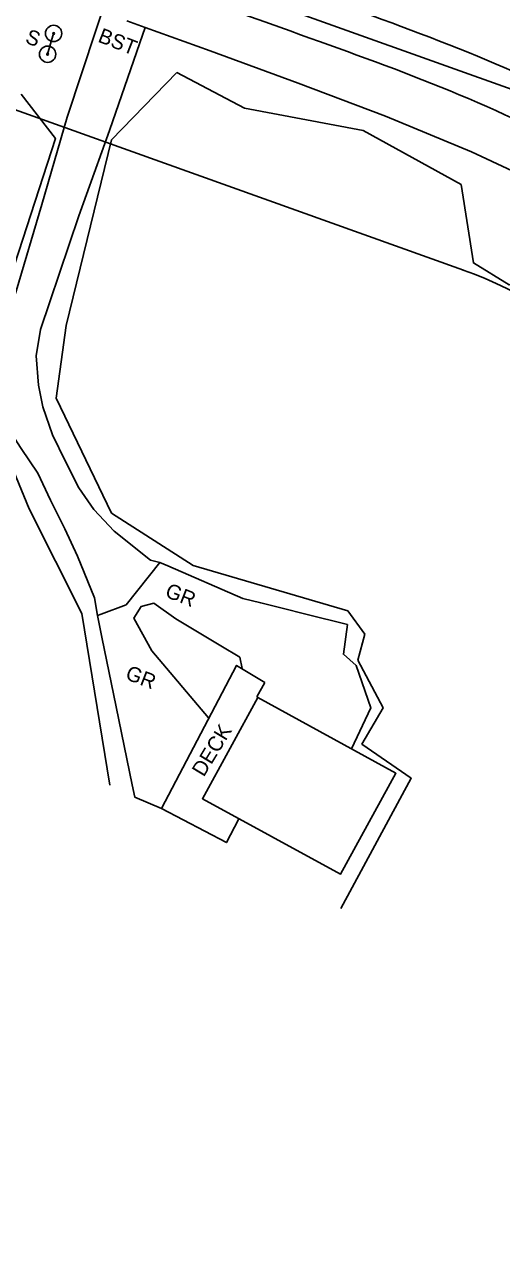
# Model space of a CAD drawing. Extents: x 1008788 to 1016064, y 551723 to 553552.
# Drawn here: x 1010480.5 to 1010608.2, y 552027.5 to 552357.7 of the extents above; entities that cross this region are included whole.
import ezdxf

# ---------------------------------------------------------------- set-up
doc = ezdxf.new("R2010")
doc.units = 0
for name, color, linetype in [('Default', 7, 'Continuous'), ('Exist Building', 7, 'Continuous'), ('Exist Horizontal Alignment', 7, 'Continuous'), ('Exist Hydro Jurisdictional Stream or Body of Water', 7, 'Continuous'), ('Exist Other Culture Area Outline', 7, 'Continuous'), ('Exist Other Culture Area Outline Text', 7, 'Continuous'), ('Exist Other Culture Sign', 7, 'Continuous'), ('Exist Other Culture Sign Post CELL', 7, 'Continuous'), ('Exist Other Culture Sign Post Text', 7, 'Continuous'), ('Exist Right of Way Line', 7, 'Continuous'), ('Exist Roads EOP', 7, 'Continuous'), ('Exist Roads EOP Text', 7, 'Continuous'), ('Exist Roads EOT', 7, 'Continuous'), ('Exist Roads Soil', 7, 'Continuous'), ('Exist Vegetation Woods Line', 7, 'Continuous')]:
    doc.layers.add(name, color=color, linetype=linetype)

msp = doc.modelspace()

# ---------------------------------------------------------------- linework, layer by layer
at = {"layer": 'Default'}
msp.add_line((1010542.68, 552177.45), (1010543.01, 552177.27), dxfattribs=at)
at = {"layer": 'Exist Building'}
msp.add_lwpolyline([(1010543.01, 552177.27), (1010528.14, 552150.15), (1010565.11, 552129.89), (1010579.98, 552157.01)], close=True, dxfattribs=at)
at = {"layer": 'Exist Horizontal Alignment'}
msp.add_line((1010173.46, 552496.9), (1010614.87, 552338.98), dxfattribs=at)
at = {"layer": 'Exist Hydro Jurisdictional Stream or Body of Water'}
for points in [[(1010381.39, 552184.09), (1010380.78, 552177.63), (1010376.79, 552166.66), (1010375.09, 552163.04), (1010364.03, 552152.1), (1010348.76, 552138.73), (1010344.64, 552132.9), (1010341.16, 552124.93), (1010337.83, 552120.24), (1010334.99, 552112.32), (1010332.71, 552102.72), (1010337.05, 552098.09), (1010348.57, 552089.19), (1010354.8, 552086.15), (1010357.97, 552085.41), (1010364.1, 552083.46), (1010370.26, 552079.74), (1010373.36, 552075.49), (1010375.69, 552072.38), (1010378.02, 552069.44), (1010379.96, 552066.84), (1010387.85, 552058.68), (1010393.84, 552052.2), (1010410.64, 552036.61), (1010420.54, 552025.11), (1010431.76, 552012.07), (1010434.15, 551991.51), (1010436.02, 551981.65), (1010448.72, 551968.73), (1010479.67, 551948.18), (1010514.9, 551929.07), (1010526.62, 551923.54), (1010540, 551923.87), (1010550.86, 551922.89), (1010596.47, 551920.92), (1010599.85, 551924.82), (1010607.7, 551927.96), (1010612.28, 551929.56), (1010619.74, 551930.02), (1010626.47, 551930.03), (1010635.11, 551930.39), (1010652.92, 551937.18), (1010670.3, 551941.43), (1010673.74, 551942.36), (1010677.15, 551943.28), (1010684.93, 551944.2), (1010692.77, 551945.58), (1010701.61, 551946.48), (1010707.07, 551947.48), (1010726.84, 551951.7), (1010738.54, 551950.28), (1010762.45, 551954.73), (1010770.85, 551958.63), (1010774.68, 551960.54), (1010778.58, 551961.26), (1010783.16, 551960.8), (1010794.54, 551961.57), (1010801, 551966.79), (1010803.09, 551970.9), (1010804.43, 551974.03)], [(1010361.81, 552091.58), (1010362.67, 552090.37), (1010363.74, 552089.63), (1010364.93, 552089.02), (1010366.18, 552088.2), (1010367.34, 552087.26), (1010368.57, 552086.34), (1010371.14, 552084.46), (1010373.68, 552082.51), (1010376, 552080.43), (1010378, 552078.28), (1010379.86, 552076.1), (1010381.7, 552073.92), (1010383.64, 552071.75), (1010384.88, 552070.48), (1010386.18, 552069.22), (1010388.91, 552066.75), (1010391.7, 552065.66), (1010395.03, 552065.68), (1010398.3, 552065.59), (1010399.73, 552065.12), (1010400.94, 552064.16), (1010403.92, 552059.12), (1010405.77, 552053.64), (1010405.97, 552052.71), (1010406.04, 552051.74), (1010406.06, 552049.76), (1010406.25, 552047.87), (1010407.07, 552046.24), (1010409.3, 552044.04), (1010411.66, 552042), (1010416.84, 552037.36), (1010419.49, 552035.1), (1010420.86, 552034.02), (1010422.27, 552032.98), (1010430.73, 552028.19), (1010439.61, 552024.19), (1010444.79, 552021.77), (1010449.98, 552019.39), (1010455.24, 552017.2), (1010457.91, 552016.21), (1010460.64, 552015.33), (1010463.41, 552014.69), (1010464.81, 552014.46), (1010466.21, 552014.25), (1010472.17, 552013.44), (1010478.13, 552012.75), (1010484.1, 552012.05), (1010490.05, 552011.22), (1010499.68, 552009.44), (1010509.21, 552007.23), (1010518.65, 552004.61), (1010523.34, 552003.16), (1010528, 552001.62), (1010535.49, 551998.37), (1010542.66, 551994.41), (1010549.85, 551990.56), (1010553.56, 551988.94), (1010557.4, 551987.65), (1010563.32, 551986.01)]]:
    msp.add_spline(points, degree=3, dxfattribs=at)
at = {"layer": 'Exist Other Culture Area Outline'}
msp.add_line((1010544.81, 552181.34), (1010542.68, 552177.45), dxfattribs=at)
msp.add_lwpolyline([(1010544.81, 552181.34), (1010537.27, 552185.91), (1010517.16, 552147.51), (1010534.54, 552138.4), (1010537.77, 552144.57)], dxfattribs=at)
at = {"layer": 'Exist Other Culture Sign'}
for centre, radius in [((1010488.27, 552355.36), 2.18), ((1010488.27, 552355.36), 0.24), ((1010486.66, 552349.79), 2.18), ((1010486.66, 552349.79), 0.24)]:
    msp.add_circle(centre, radius, dxfattribs=at)
at = {"layer": 'Exist Other Culture Sign Post CELL'}
msp.add_line((1010486.66, 552349.79), (1010488.27, 552355.36), dxfattribs=at)
at = {"layer": 'Exist Right of Way Line'}
msp.add_line((1010156.62, 552449.83), (1010598.03, 552291.9), dxfattribs=at)
msp.add_arc((1010559.96, 552185.51), 113, 19.6597, 70.3142, dxfattribs=at)
at = {"layer": 'Exist Roads EOP'}
for points in [[(1010499.98, 552199.29), (1010499.19, 552204.05), (1010494.64, 552215.24), (1010491.3, 552222.5), (1010487.41, 552230.26), (1010484.07, 552237.42), (1010479.58, 552244.06), (1010474.55, 552251.83), (1010473.54, 552261.55), (1010473.43, 552269.75), (1010475.77, 552278.85), (1010478.21, 552286.22), (1010485.11, 552309.51), (1010491.88, 552332.93), (1010499.66, 552356.46), (1010501.15, 552361)], [(1010516.76, 552213.52), (1010514.18, 552214.1), (1010504.52, 552221.87), (1010499.02, 552227.67), (1010494.98, 552233.53), (1010491.45, 552240.61), (1010487.98, 552247.71), (1010485.37, 552255.2), (1010484.2, 552261.02), (1010483.6, 552268.96), (1010484.78, 552276.02), (1010487.23, 552283.44), (1010495, 552306.5), (1010503.24, 552329.38), (1010511.35, 552352.81), (1010512.77, 552356.97)], [(1010507.88, 552358.72), (1010512.77, 552356.97), (1010530.23, 552350.74), (1010553.74, 552342.07), (1010577.14, 552333.2), (1010600.23, 552323.63), (1010611.07, 552318.54)]]:
    msp.add_lwpolyline(points, dxfattribs=at)
at = {"layer": 'Exist Roads EOT'}
for points in [[(1009326.37, 552370.41), (1009366.27, 552398.88), (1009433, 552444.3), (1009491.08, 552478), (1009564.84, 552504.9), (1009641.76, 552517.42), (1009690.56, 552517.42), (1009731.11, 552514.26), (1009771.43, 552511.25), (1009839.62, 552511.9), (1009890.37, 552515.91), (1009962.05, 552522.29), (1010007.86, 552525.04), (1010075.8, 552524.16), (1010152.39, 552509.17), (1010200.72, 552493.87), (1010265.31, 552471.49), (1010354.4, 552439.56), (1010494.37, 552389.09), (1010565.98, 552362.91), (1010606.86, 552347.16), (1010639.67, 552332.06)], [(1009324.04, 552354.2), (1009373.22, 552388.85), (1009463.13, 552447.43), (1009542.62, 552483.7), (1009611.32, 552501.27), (1009670.39, 552505.71), (1009723.46, 552501.51), (1009773.73, 552496.65), (1009840.03, 552498.42), (1009903.5, 552504.93), (1009981.25, 552511.39), (1010048.94, 552513.35), (1010148.66, 552497.6), (1010220.28, 552474.37), (1010346.77, 552429.96), (1010465.58, 552387.02), (1010554.42, 552355.03), (1010632.85, 552321.3), (1010671.42, 552291.73), (1010696.96, 552257.59), (1010718.18, 552214.53), (1010737.26, 552167.75), (1010750.68, 552139.43)]]:
    msp.add_spline(points, degree=3, dxfattribs=at)
at = {"layer": 'Exist Roads Soil'}
for points in [[(1010566.97, 552196.87), (1010555.86, 552199.65), (1010549.48, 552201.25), (1010543.75, 552202.68), (1010538.97, 552203.88), (1010518.88, 552212.59), (1010516.76, 552213.52), (1010507.68, 552202.14), (1010500.96, 552199.66), (1010499.98, 552199.29), (1010501.17, 552193.49), (1010505.03, 552174.81), (1010509.35, 552153.86), (1010510.02, 552150.61), (1010517.14, 552147.51)], [(1010529.74, 552171.87), (1010514.6, 552189.84), (1010509.76, 552198.62), (1010511.69, 552201.67), (1010515.15, 552202.64), (1010521.03, 552198.42), (1010533.09, 552191.16), (1010538.17, 552188.11), (1010538.74, 552185.06)], [(1010566.97, 552196.87), (1010565.91, 552188.91), (1010569.29, 552185.89), (1010573.24, 552174.51), (1010568.1, 552163.53)]]:
    msp.add_lwpolyline(points, dxfattribs=at)
at = {"layer": 'Exist Vegetation Woods Line'}
for points in [[(1010565.17, 552120.75), (1010584.09, 552155.64), (1010570.84, 552164.83), (1010576.52, 552174.57), (1010569.76, 552187.28), (1010571.65, 552194.31), (1010567.06, 552200.53), (1010525.69, 552212.7), (1010503.8, 552226.76), (1010488.93, 552257.59), (1010491.63, 552277.06), (1010503.8, 552326.82), (1010521.27, 552344.92)], [(1010521.27, 552344.92), (1010539.39, 552335.37), (1010571.21, 552329.35), (1010597.47, 552314.82), (1010600.72, 552293.81), (1010610.29, 552287.93), (1010634.86, 552297.36), (1010656.95, 552278.04), (1010675.02, 552256.1), (1010691.44, 552225.83), (1010706.31, 552189.05), (1010716.92, 552164.34), (1010718.29, 552144.41), (1010729.88, 552119.99), (1010739.3, 552100.52), (1010759.69, 552081.67), (1010777.92, 552060.5), (1010800.32, 552056.94), (1010815.77, 552036.97), (1010817.93, 552016.42)], [(1010479.56, 552339.07), (1010488.75, 552327.17), (1010473.34, 552279.85)], [(1010471.18, 552253.34), (1010481.72, 552227.93), (1010495.78, 552199.8), (1010503.35, 552153.83)]]:
    msp.add_lwpolyline(points, dxfattribs=at)

# ---------------------------------------------------------------- texts
at = {"layer": 'Exist Other Culture Area Outline Text'}
msp.add_text('DECK', height=4, rotation=58.7796, dxfattribs=at).set_placement((1010528.48, 552155.81))
at = {"layer": 'Exist Other Culture Sign Post Text'}
msp.add_text('S', height=4, rotation=339.0225, dxfattribs=at).set_placement((1010480.41, 552352.94))
at = {"layer": 'Exist Roads EOP Text'}
for s, p in [('BST', (1010499.88, 552353.21)), ('GR', (1010517.87, 552204.4)), ('GR', (1010507.23, 552182.34))]:
    msp.add_text(s, height=4, rotation=338.6928, dxfattribs=at).set_placement(p)

doc.saveas('drawing.dxf')
